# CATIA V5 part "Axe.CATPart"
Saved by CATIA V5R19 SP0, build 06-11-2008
Part number: Axe
Publications: "L_axe"
Bounding box of the stored display mesh (mm): x -8 to 275, y -5 to 5, z -4 to 5
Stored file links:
  G:\EU_thinkMotion\CFAO_2010\MMS_groupe3\MMS_groupe3\A reprendre\evulliez\evulliez\Axe.CATPart
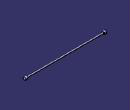
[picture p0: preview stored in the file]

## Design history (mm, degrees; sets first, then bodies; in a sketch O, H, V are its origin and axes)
Parameters
  L_axe = 267 mm
Body1 (main body)
  Sketch1 on yz-plane, origin (0, 0, 0), H (0, 1, 0), V (0, 0, 1)
    circle A1 centre (0, 0) radius 2.5
    radius A1 = 2.5
  Pad1: profile Sketch1, direction (1, 0, 0), length 267 {= L_axe}
  Sketch2 on end face of Pad1, origin (267, 0, 0), H (0, 1, 0), V (0, 0, 1)
    circle A1 centre (0, 0) radius 5
    radius A1 = 5
  Pad2: profile Sketch2, direction (1, 0, 0), length 8
  Sketch3 on start face of Pad1, origin (0, 0, 0), H (0, -1, 0), V (0, 0, 1)
    circle A1 centre (0, 0) radius 5
    radius A1 = 5
  Pad3: profile Sketch3, direction (-1, 0, 0), length 8
  Plane1: type Offset, RefPlane xy-plane, Offset 4, reversed
  Split1: SplitPlane Plane1
  Point1: type OnPlane, Support face of Split1, H 271 {= L_axe +4mm}, V 0, Direction (1, 0, 0)
  Point2: type OnPlane, Support face of Split1, H -4, V 0, Direction (1, 0, 0)
  Sketch4 on face of Split1, origin (55, 0, -4), H (1, 0, 0), V (0, -1, 0)
    point P1 (216, 0)
    reference projected point E1 (216, 0) from Point1
    coincidence: E1 P1
  Hole1: placed by Sketch4, at (271, 0, -4) direction (0, 0, 1), diameter 5, depth 3
  Sketch5 on face of Split1, origin (-5, 0, -4), H (1, 0, 0), V (0, -1, 0)
    point P1 (1, 0)
    reference projected point E1 (1, 0) from Point2
    coincidence: E1 P1
  Hole2: placed by Sketch5, at (-4, 0, -4) direction (0, 0, 1), diameter 5, depth 3
  Point3: (271, 0, -2.5)
  Line1: type PtDir, RefPoint Point3, Direction (0, 1, 0), Start -20, End 20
